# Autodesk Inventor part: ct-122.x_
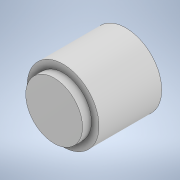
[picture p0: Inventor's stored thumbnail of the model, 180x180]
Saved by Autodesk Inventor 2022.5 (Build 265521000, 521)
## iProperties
Created: 2023-06
Part Number: ct-122.x_
Material: Generic
Document SubType Name: Modeling
Designer: ImaoCorp
Density: 1 g/cm^3
Appearance: Default
Sending System: SOLIDWORKS 2021-2021301
MC: AMD64
MC_MODEL: Intel64 Family 6 Model 60 Stepping 3, GenuineIntel
OS: Windows_NT
FRU: Parasolid Version 32.1, build 255,  1- 1-2021
FORMAT: text
GUISE: transmit
KEY: ct-122
FILE: ct-122.x_t
DATE: Thu Jun 15 15:47:26 2023
Author: ImaoCorp
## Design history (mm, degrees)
feature "Base1"
node "ソリッド1"
